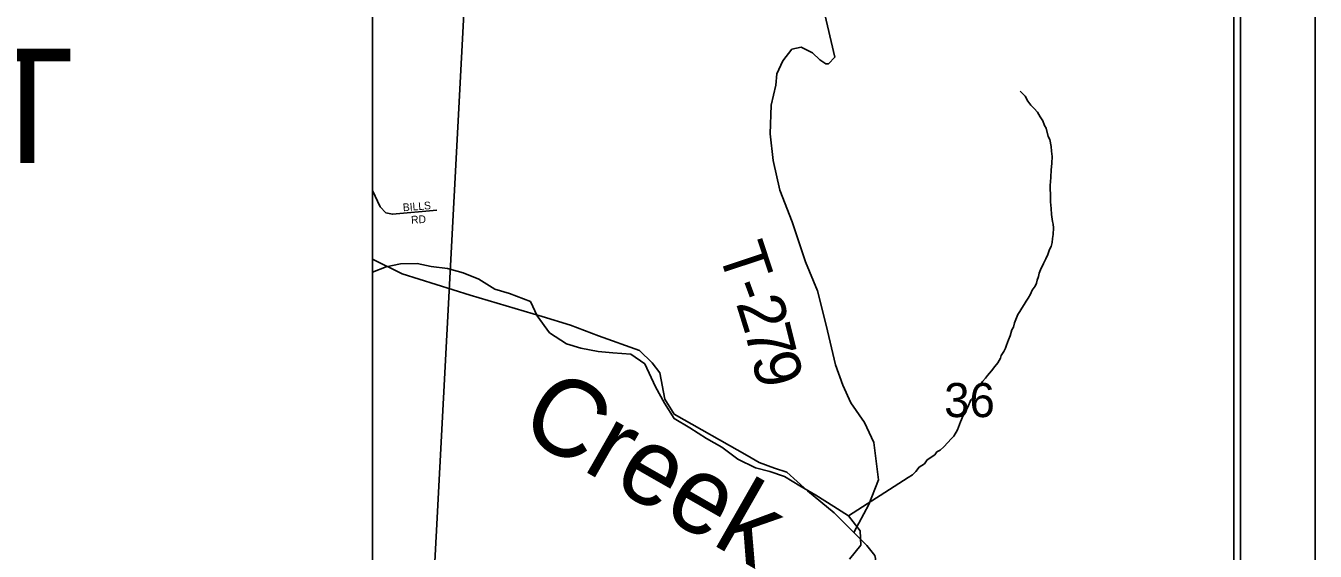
# Model space of a CAD drawing. Extents: x 0 to 34, y 0 to 22.
# Drawn here: x 7.417 to 9, y 16.08 to 16.725 of the extents above; entities that cross this region are included whole.
import ezdxf

# ---------------------------------------------------------------- set-up
doc = ezdxf.new("R2010")
doc.units = 0
for name, color, linetype in [('GM_X_County', 7, 'Continuous'), ('GM_X_County_Road', 7, 'Continuous'), ('GM_X_Minor_River', 7, 'Continuous'), ('GM_X_Minor_River_Text', 7, 'Continuous'), ('GM_X_Section', 7, 'Continuous'), ('GM_X_Section_Text', 7, 'Continuous'), ('GM_X_Township', 7, 'Continuous'), ('GM_X_Township_Road', 7, 'Continuous'), ('GM_X_Township_Road_Text', 7, 'Continuous'), ('GM_X_Township_Subdivision', 7, 'Continuous'), ('GM_X_Township_Subdivision_Text', 7, 'Continuous'), ('SH_Data', 7, 'Continuous'), ('SH_Text', 7, 'Continuous')]:
    doc.layers.add(name, color=color, linetype=linetype)

msp = doc.modelspace()

# ---------------------------------------------------------------- linework, layer by layer
at = {"layer": 'GM_X_County'}
msp.add_lwpolyline([(8.9084, 15.63), (8.9084, 20.8908), (2.1084, 20.8908), (2.1084, 19.9847)], dxfattribs=at)
at = {"layer": 'GM_X_County_Road'}
msp.add_lwpolyline([(7.8426, 16.4384), (7.879, 16.4205), (7.9624, 16.3946), (8.051, 16.3683), (8.0855, 16.3577), (8.1199, 16.3444), (8.1703, 16.3265), (8.1858, 16.3113), (8.1953, 16.2991), (8.2014, 16.2668), (8.2131, 16.2486), (8.3025, 16.1976), (8.3173, 16.1892), (8.3362, 16.182), (8.3513, 16.1774), (8.3768, 16.1545), (8.4092, 16.1276), (8.4334, 16.1031), (8.4496, 16.0872), (8.4594, 16.0751), (8.4601, 16.0712), (8.4624, 16.0506), (8.467, 15.9639), (8.4705, 15.9381)], dxfattribs=at)
at = {"layer": 'GM_X_Minor_River'}
for points in [[(8.6439, 16.6387), (8.6379, 16.6445)], [(8.4269, 16.1237), (8.5001, 16.1708), (8.5055, 16.1742), (8.5097, 16.1783), (8.5136, 16.1835), (8.5201, 16.1876), (8.5236, 16.1925), (8.5328, 16.1984), (8.5355, 16.2022), (8.5397, 16.2044), (8.544, 16.2085), (8.549, 16.2137), (8.5532, 16.2182), (8.5563, 16.2216), (8.5606, 16.2291), (8.5646, 16.2389), (8.5677, 16.2468), (8.5712, 16.2525), (8.5736, 16.257), (8.5772, 16.2661), (8.5803, 16.2698), (8.5838, 16.2781), (8.5884, 16.283), (8.5916, 16.2886), (8.595, 16.2924), (8.5978, 16.2957), (8.6024, 16.3017), (8.6067, 16.307), (8.6105, 16.3115), (8.6137, 16.3171), (8.6145, 16.3205), (8.6176, 16.3254), (8.6199, 16.3292), (8.6208, 16.333), (8.6235, 16.3398), (8.6255, 16.3447), (8.6275, 16.3519), (8.6295, 16.3553), (8.6307, 16.3606), (8.6347, 16.3708), (8.6374, 16.3745), (8.6397, 16.3783), (8.6425, 16.3828), (8.6452, 16.3869), (8.6475, 16.3907), (8.6506, 16.3956), (8.6526, 16.4005), (8.6561, 16.4054), (8.6577, 16.4091), (8.6585, 16.4126), (8.6601, 16.4171), (8.6609, 16.4213), (8.6629, 16.4254), (8.6664, 16.4333), (8.6692, 16.439), (8.6719, 16.4443), (8.6739, 16.4503), (8.6759, 16.4541), (8.6771, 16.459), (8.6776, 16.4639), (8.6784, 16.4689), (8.6786, 16.4769), (8.6783, 16.4814), (8.6776, 16.4849), (8.6762, 16.4932), (8.6756, 16.5009), (8.675, 16.5089), (8.6751, 16.5176), (8.6745, 16.5252), (8.6746, 16.5298), (8.675, 16.5332), (8.6755, 16.5396), (8.676, 16.5476), (8.6765, 16.5564), (8.6771, 16.5643), (8.6764, 16.5712), (8.6758, 16.5769), (8.674, 16.5853), (8.6722, 16.5891), (8.6697, 16.5991), (8.6675, 16.6025), (8.6657, 16.6083), (8.6624, 16.6133), (8.6591, 16.6187), (8.655, 16.6233), (8.6509, 16.6275), (8.6472, 16.6322), (8.6439, 16.6387)], [(8.4282, 16.0705), (8.4419, 16.0879), (8.4412, 16.1054), (8.4269, 16.1237), (8.4088, 16.1351), (8.3869, 16.1489), (8.3672, 16.1604), (8.3484, 16.1718), (8.3302, 16.178), (8.3128, 16.1826), (8.2909, 16.1933), (8.2713, 16.2078), (8.2524, 16.2185), (8.232, 16.2315), (8.2131, 16.243), (8.201, 16.262), (8.1898, 16.2818), (8.177, 16.31), (8.1596, 16.3222), (8.1377, 16.3238), (8.1195, 16.3254), (8.0983, 16.3293), (8.0809, 16.3347), (8.0598, 16.3484), (8.0447, 16.369), (8.0364, 16.3865), (8.0107, 16.3965), (7.9926, 16.4019), (7.9729, 16.4141), (7.954, 16.4218), (7.9344, 16.4272), (7.9147, 16.4296), (7.8973, 16.4334), (7.8768, 16.4327), (7.8594, 16.429), (7.8426, 16.4226)]]:
    msp.add_lwpolyline(points, dxfattribs=at)
at = {"layer": 'GM_X_Section'}
msp.add_line((8.9084, 15.7545), (8.9084, 16.7577), dxfattribs=at)
for points in [[(6.8391, 16.7743), (6.8455, 16.8788), (7.9583, 16.8099), (7.9053, 15.8044), (6.7831, 15.8661), (6.795, 16.0591)], [(8.9084, 16.7577), (7.9583, 16.8099), (7.9053, 15.8044), (8.9084, 15.7545)]]:
    msp.add_lwpolyline(points, dxfattribs=at)
at = {"layer": 'GM_X_Township'}
msp.add_lwpolyline([(8.9084, 15.63), (8.9084, 20.8908), (5.9855, 20.8908)], dxfattribs=at)
at = {"layer": 'GM_X_Township_Road'}
msp.add_lwpolyline([(8.4334, 16.1031), (8.4521, 16.1375), (8.4638, 16.1679), (8.4626, 16.1778), (8.4582, 16.2135), (8.4464, 16.2382), (8.4298, 16.2625), (8.4199, 16.2842), (8.4108, 16.3089), (8.3995, 16.3575), (8.3889, 16.3997), (8.3741, 16.4354), (8.3578, 16.4844), (8.3427, 16.5232), (8.3343, 16.5597), (8.3309, 16.5924), (8.3321, 16.6274), (8.3377, 16.6521), (8.3389, 16.6658), (8.3464, 16.6818), (8.3574, 16.6962), (8.3688, 16.6985), (8.3828, 16.6916), (8.3919, 16.6832), (8.3991, 16.6783), (8.4025, 16.6783), (8.4101, 16.6863), (8.3786, 16.8213)], dxfattribs=at)
at = {"layer": 'GM_X_Township_Subdivision'}
msp.add_lwpolyline([(7.8426, 16.5226), (7.8518, 16.5028), (7.8587, 16.4955), (7.867, 16.4937), (7.9213, 16.4985)], dxfattribs=at)
at = {"layer": 'SH_Data'}
for p, q in [((9, 21), (9, 14)), ((8.9, 20.9), (8.9, 14.1))]:
    msp.add_line(p, q, dxfattribs=at)
at = {"layer": 'SH_Text'}
msp.add_lwpolyline([(6.0532, 16.7743), (7.8426, 16.7743), (7.8426, 16.0591), (6.0532, 16.0591)], close=True, dxfattribs=at)

# ---------------------------------------------------------------- texts
at = {"layer": 'GM_X_Minor_River_Text'}
msp.add_text('Creek', height=0.09471, rotation=330.2117, dxfattribs=at).set_placement((8.0191, 16.2263))
at = {"layer": 'GM_X_Section_Text'}
msp.add_text('36', height=0.04186, rotation=0, dxfattribs=at).set_placement((8.5444, 16.2448))
at = {"layer": 'GM_X_Township_Road_Text'}
for s, rotation, p in [('T', 288.3367, (8.2665, 16.4482)), ('-', 290.4631, (8.2806, 16.4057)), ('2', 287.3429, (8.2885, 16.3846)), ('7', 283.9807, (8.2987, 16.352)), ('9', 284.5034, (8.3073, 16.3175))]:
    msp.add_text(s, height=0.0568, rotation=rotation, dxfattribs=at).set_placement(p)
at = {"layer": 'GM_X_Township_Subdivision_Text'}
for s, rotation, p in [('BILLS', 4.3986, (7.8801, 16.4973)), ('RD', 3.0124, (7.8901, 16.4821))]:
    msp.add_text(s, height=0.00947, rotation=rotation, dxfattribs=at).set_placement(p)
at = {"layer": 'SH_Text'}
msp.add_text('END PROJECT', height=0.14, dxfattribs=at).set_placement((6.1549, 16.5567))

doc.saveas('drawing.dxf')
